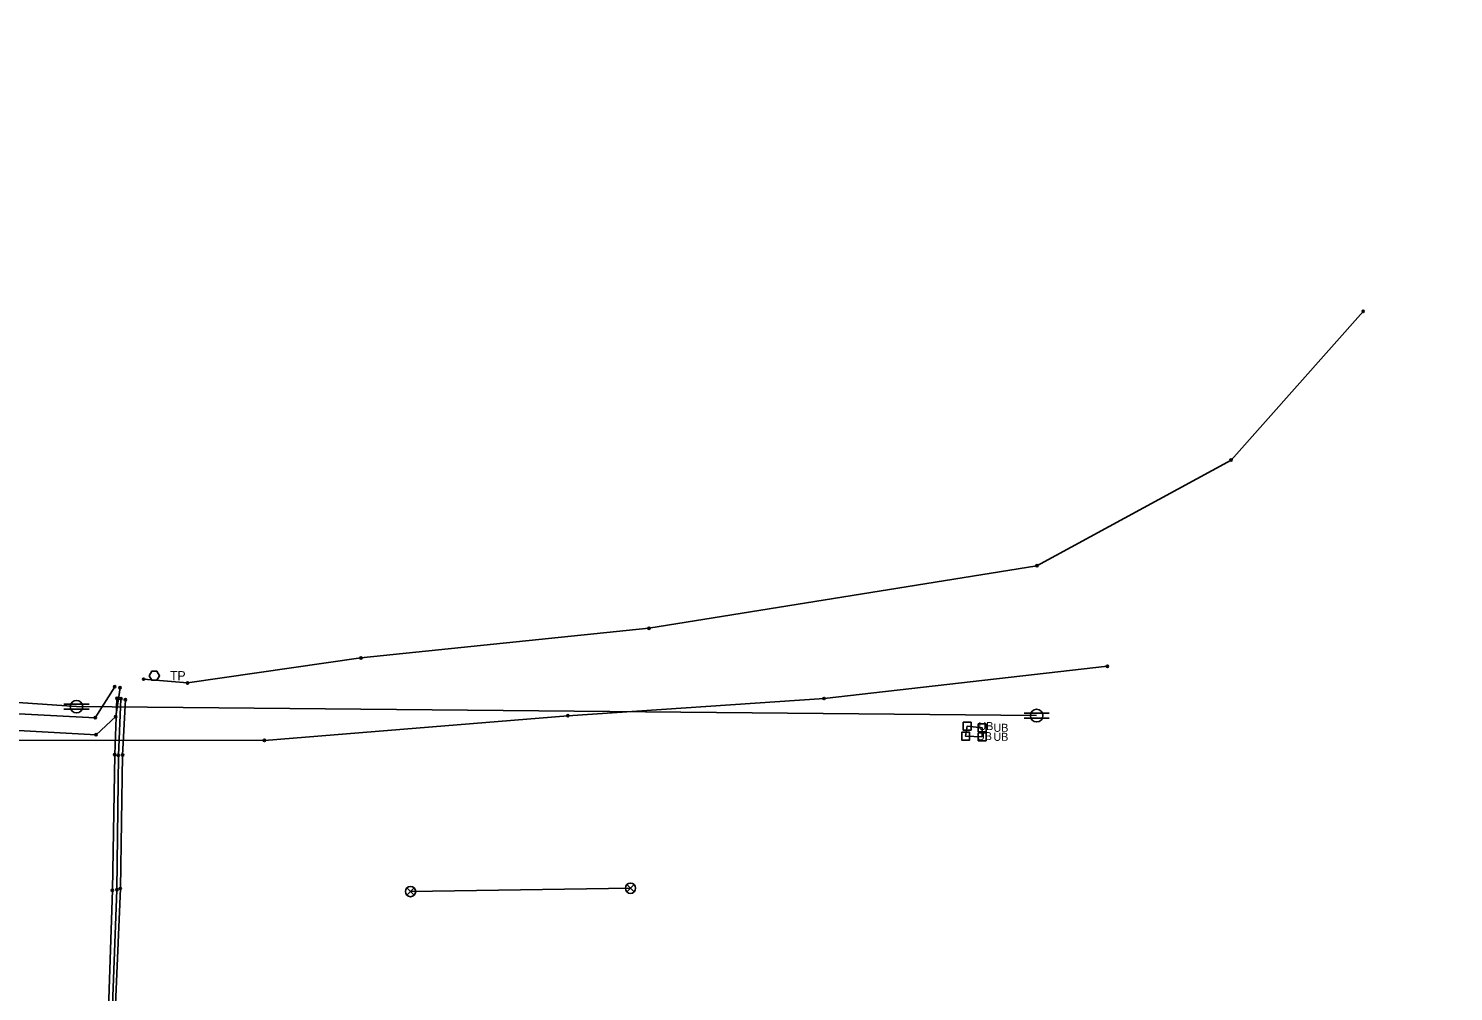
# Model space of a CAD drawing. Extents: x 20500343 to 20505311, y 7953484 to 7954193.
# Drawn here: x 20504997.9 to 20505247, y 7953652.3 to 7953820.7 of the extents above; entities that cross this region are included whole.
import ezdxf

# ---------------------------------------------------------------- set-up
doc = ezdxf.new("R2010")
doc.units = 0
for name, color, linetype in [('C-PROP-LINE-LOT', 7, 'Continuous'), ('V-ANNO-NOTE', 7, 'Continuous'), ('V-CTRL-HVPT', 7, 'Continuous'), ('V-MON-FND', 7, 'Continuous'), ('V-SITE-FENC', 7, 'Continuous'), ('V-SSWR-STRC', 7, 'Continuous')]:
    doc.layers.add(name, color=color, linetype=linetype)

msp = doc.modelspace()

# ---------------------------------------------------------------- linework, layer by layer
at = {"layer": 'C-PROP-LINE-LOT'}
for points in [[(20503437.68, 7953820.69), (20503685.54, 7953801.97), (20503900.73, 7953784.06), (20504174.6, 7953760.81), (20504420.99, 7953738.08), (20504670.9, 7953722.47), (20504838.2, 7953713.61), (20505006.28, 7953702.11), (20505174.11, 7953700.54)], [(20503699.26, 7953775.1), (20503803.54, 7953764.58), (20503866.33, 7953759.03), (20503928.53, 7953761.61), (20504053.64, 7953746.16), (20504141.91, 7953734.18), (20504242.25, 7953732.31), (20504268.23, 7953730.01), (20504338.72, 7953728.07), (20504367.8, 7953726.96), (20504422.51, 7953721.81), (20504479.99, 7953718.52), (20504541.43, 7953712.4), (20504605.71, 7953707.78), (20504671.49, 7953704.84), (20504755.78, 7953700.92), (20504815.67, 7953699.69), (20504872.03, 7953696.31), (20505039.13, 7953696.21), (20505092.16, 7953700.52), (20505136.96, 7953703.53), (20505186.48, 7953709.16)], [(20505018.01, 7953706.91), (20505025.68, 7953706.26), (20505056, 7953710.62), (20505106.33, 7953715.82), (20505174.15, 7953726.75), (20505208.11, 7953745.22), (20505231.19, 7953771.21)], [(20504210.51, 7953740.4), (20504276.78, 7953736.15), (20504317.11, 7953736.51), (20504358.06, 7953737.31), (20504412.3, 7953733.34), (20504478.84, 7953727.73), (20504548.56, 7953722.54), (20504593.65, 7953719.05), (20504644.38, 7953715.53), (20504690.36, 7953713.78), (20504723.6, 7953712.89), (20504765.96, 7953712.31), (20504818.14, 7953709.88), (20504868.03, 7953706.56), (20504918.85, 7953702.08), (20504975.03, 7953699.08), (20505009.69, 7953697.2), (20505013.14, 7953700.37), (20505013.9, 7953705.42)], [(20504691.32, 7953722.32), (20504725.14, 7953720.68), (20504766.04, 7953714.69), (20504818.85, 7953712.46), (20504867.86, 7953709.05), (20504920.37, 7953706.07), (20504974.93, 7953701.95), (20505009.55, 7953700.17), (20505012.95, 7953705.6)], [(20505013.33, 7953703.56), (20505012.96, 7953693.72), (20505012.56, 7953669.99), (20505011.56, 7953640.51), (20505008.67, 7953604.85), (20505007.2, 7953575.58), (20505007.69, 7953565.88), (20505042.73, 7953559.05), (20505069.33, 7953557.97), (20505121.95, 7953555.03), (20505162.59, 7953553.57), (20505190.61, 7953553.26), (20505211.07, 7953551.49), (20505229.15, 7953547.86)], [(20505014.04, 7953703.48), (20505013.59, 7953693.59), (20505013.35, 7953670.1), (20505012.2, 7953640.55), (20505009.2, 7953604.9), (20505007.97, 7953575.58), (20505008.15, 7953565.68), (20505067.6, 7953566.47), (20505122.4, 7953562.4), (20505180.36, 7953565.69), (20505230.56, 7953560.95), (20505246.98, 7953564.46)], [(20505014.82, 7953703.33), (20505014.33, 7953693.64), (20505013.94, 7953670.31), (20505012.67, 7953640.54), (20505009.65, 7953605.21), (20505008.65, 7953575.55), (20505009.1, 7953566.88), (20505043.47, 7953567.1), (20505069.5, 7953568.67), (20505122.66, 7953563.23), (20505162.48, 7953561.76), (20505191.13, 7953560.15), (20505231.08, 7953557.04)], [(20505064.67, 7953669.77), (20505103.12, 7953670.35)]]:
    msp.add_lwpolyline(points, dxfattribs=at)
at = {"layer": 'V-ANNO-NOTE'}
for centre in [(20505231.19, 7953771.21), (20505208.11, 7953745.22), (20505174.15, 7953726.75), (20505106.33, 7953715.82), (20505056, 7953710.62), (20505186.48, 7953709.16), (20505012.95, 7953705.6), (20505013.9, 7953705.42), (20505018.01, 7953706.91), (20505025.68, 7953706.26), (20505013.33, 7953703.56), (20505014.04, 7953703.48), (20505014.82, 7953703.33), (20505136.96, 7953703.53), (20505009.55, 7953700.17), (20505013.14, 7953700.37), (20505092.16, 7953700.52), (20505009.69, 7953697.2), (20505039.13, 7953696.21), (20505012.96, 7953693.72), (20505013.59, 7953693.59), (20505014.33, 7953693.64), (20505012.56, 7953669.99), (20505013.35, 7953670.1), (20505013.94, 7953670.31)]:
    msp.add_circle(centre, 0.2, dxfattribs=at)
at = {"layer": 'V-CTRL-HVPT'}
for p, q in [((20505004.08, 7953702.55), (20505008.48, 7953702.55)), ((20505004.08, 7953701.67), (20505008.48, 7953701.67)), ((20505171.91, 7953700.98), (20505176.31, 7953700.98)), ((20505171.91, 7953700.1), (20505176.31, 7953700.1))]:
    msp.add_line(p, q, dxfattribs=at)
for centre in [(20505006.28, 7953702.11), (20505174.11, 7953700.54)]:
    msp.add_circle(centre, 1.1, dxfattribs=at)
at = {"layer": 'V-MON-FND'}
msp.add_lwpolyline([(20505018.97, 7953707.52), (20505019.42, 7953708.31), (20505020.34, 7953708.31), (20505020.79, 7953707.52), (20505020.34, 7953706.73), (20505019.42, 7953706.73), (20505018.97, 7953707.52)], dxfattribs=at)
msp.add_lwpolyline([(20505164.58, 7953696.81), (20505161.7, 7953696.94), (20505161.96, 7953698.69), (20505164.59, 7953698.39)], close=True, dxfattribs=at)
msp.add_lwpolyline([(20505164.58, 7953696.81), (20505161.7, 7953696.94), (20505161.96, 7953698.69), (20505164.59, 7953698.39)], close=True, dxfattribs=at)
at = {"layer": 'V-SITE-FENC'}
for points in [[(20505161.7, 7953696.25), (20505161.7, 7953696.25), (20505162.39, 7953696.25), (20505162.39, 7953697.62), (20505161.01, 7953697.62), (20505161.01, 7953696.25), (20505161.7, 7953696.25)], [(20505161.96, 7953698), (20505161.96, 7953698), (20505162.65, 7953698), (20505162.65, 7953699.37), (20505161.27, 7953699.37), (20505161.27, 7953698), (20505161.96, 7953698)], [(20505164.58, 7953696.13), (20505164.58, 7953696.13), (20505165.27, 7953696.13), (20505165.27, 7953697.5), (20505163.89, 7953697.5), (20505163.89, 7953696.13), (20505164.58, 7953696.13)], [(20505164.59, 7953697.71), (20505164.59, 7953697.71), (20505165.28, 7953697.71), (20505165.28, 7953699.08), (20505163.9, 7953699.08), (20505163.9, 7953697.71), (20505164.59, 7953697.71)]]:
    msp.add_lwpolyline(points, dxfattribs=at)
at = {"layer": 'V-SSWR-STRC'}
for points in [[(20505064.03, 7953669.13), (20505064.67, 7953669.77), (20505064.03, 7953670.41)], [(20505065.31, 7953670.41), (20505064.67, 7953669.77), (20505065.31, 7953669.13)], [(20505102.48, 7953669.72), (20505103.12, 7953670.35), (20505102.48, 7953670.99)], [(20505103.76, 7953670.99), (20505103.12, 7953670.35), (20505103.76, 7953669.72)]]:
    msp.add_lwpolyline(points, dxfattribs=at)
for centre, start, end in [((20505064.67, 7953669.77), 135, 225), ((20505064.67, 7953669.77), 45, 135), ((20505064.67, 7953669.77), 315, 45), ((20505103.12, 7953670.35), 135, 225), ((20505103.12, 7953670.35), 45, 135), ((20505103.12, 7953670.35), 315, 45), ((20505064.67, 7953669.77), 225, 315), ((20505103.12, 7953670.35), 225, 315)]:
    msp.add_arc(centre, 0.899, start, end, dxfattribs=at)

# ---------------------------------------------------------------- texts
at = {"layer": 'V-MON-FND'}
msp.add_text('TP', height=1.599, dxfattribs=at).set_placement((20505022.62, 7953706.72))
at = {"layer": 'V-SITE-FENC'}
for p in [(20505163.69, 7953696.25), (20505163.95, 7953698.01), (20505166.57, 7953696.13), (20505166.58, 7953697.71)]:
    msp.add_text('UB', height=1.399, dxfattribs=at).set_placement(p)

doc.saveas('drawing.dxf')
